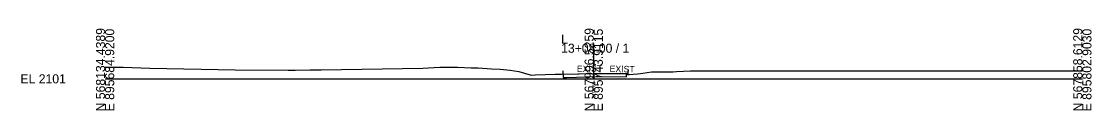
# Model space of a CAD drawing. Extents: x -26 to 1603, y -10 to 13527.
# Drawn here: x 1274.3 to 1602.8, y -9.7 to 15.4 of the extents above; entities that cross this region are included whole.
import ezdxf

# ---------------------------------------------------------------- set-up
doc = ezdxf.new("R2010")
doc.units = 0
for name, color, linetype in [('Default', 7, 'Continuous'), ('Exist XS Center Line Elevation Label', 7, 'Continuous'), ('Exist XS Ground Line', 7, 'Continuous'), ('Old_Level_61', 7, 'Continuous'), ('Old_Level_63', 7, 'Continuous'), ('Prop XS EOT Tick Mark', 7, 'Continuous'), ('Prop XS Finish Grade Pavement', 7, 'Continuous'), ('Prop XS Subgrade Earthwork', 7, 'Continuous')]:
    doc.layers.add(name, color=color, linetype=linetype)

msp = doc.modelspace()

# ---------------------------------------------------------------- linework, layer by layer
at = {"layer": 'Exist XS Ground Line'}
for p, q in [((1300, 3.54), (1300.91, 3.54)), ((1300, 3.54), (1300.91, 3.54)), ((1300.91, 3.54), (1305.5, 3.54)), ((1300.91, 3.54), (1305.5, 3.54)), ((1305.5, 3.54), (1313.77, 3.3)), ((1305.5, 3.54), (1313.77, 3.3)), ((1313.77, 3.3), (1339.93, 2.76)), ((1313.77, 3.3), (1339.93, 2.76)), ((1397.58, 3.24), (1402.75, 3.56)), ((1397.58, 3.24), (1402.75, 3.56)), ((1402.75, 3.56), (1404.84, 3.58)), ((1402.75, 3.56), (1404.84, 3.58)), ((1404.84, 3.58), (1406.91, 3.6)), ((1404.84, 3.58), (1406.91, 3.6)), ((1406.91, 3.6), (1408.21, 3.6)), ((1406.91, 3.6), (1408.21, 3.6)), ((1408.21, 3.6), (1412.37, 3.36)), ((1408.21, 3.6), (1412.37, 3.36)), ((1412.37, 3.36), (1413.97, 3.38)), ((1412.37, 3.36), (1413.97, 3.38)), ((1413.97, 3.38), (1414.55, 3.35)), ((1413.97, 3.38), (1414.55, 3.35)), ((1414.55, 3.35), (1418.66, 3.05)), ((1414.55, 3.35), (1418.66, 3.05)), ((1339.93, 2.76), (1356.24, 2.67)), ((1339.93, 2.76), (1356.24, 2.67)), ((1356.24, 2.67), (1357.3, 2.66)), ((1356.24, 2.67), (1357.3, 2.66)), ((1357.3, 2.66), (1358.38, 2.66)), ((1357.3, 2.66), (1358.38, 2.66)), ((1358.38, 2.66), (1362.94, 2.75)), ((1358.38, 2.66), (1362.94, 2.75)), ((1362.94, 2.75), (1363.26, 2.75)), ((1362.94, 2.75), (1363.26, 2.75)), ((1363.26, 2.75), (1366.29, 2.76)), ((1363.26, 2.75), (1366.29, 2.76)), ((1366.29, 2.76), (1397.58, 3.24)), ((1366.29, 2.76), (1397.58, 3.24)), ((1418.66, 3.05), (1421.26, 2.95)), ((1418.66, 3.05), (1421.26, 2.95)), ((1421.26, 2.95), (1424.33, 2.64)), ((1421.26, 2.95), (1424.33, 2.64)), ((1424.33, 2.64), (1427.05, 2.28)), ((1424.33, 2.64), (1427.05, 2.28)), ((1427.05, 2.28), (1430.45, 1.28)), ((1427.05, 2.28), (1430.45, 1.28)), ((1430.45, 1.28), (1430.89, 1.16)), ((1430.45, 1.28), (1430.89, 1.16)), ((1430.89, 1.16), (1431.99, 1.19)), ((1430.89, 1.16), (1431.99, 1.19)), ((1431.99, 1.19), (1438.2, 1.39)), ((1431.99, 1.19), (1438.2, 1.39)), ((1438.2, 1.39), (1440.11, 1.41)), ((1438.2, 1.39), (1440.11, 1.41)), ((1440.11, 1.41), (1450.1, 1.65)), ((1440.11, 1.41), (1450.1, 1.65)), ((1450.1, 1.65), (1450.79, 1.67)), ((1450.1, 1.65), (1450.79, 1.67)), ((1450.79, 1.67), (1451.38, 1.67)), ((1450.79, 1.67), (1451.38, 1.67)), ((1451.38, 1.67), (1460.05, 1.59)), ((1451.38, 1.67), (1460.05, 1.59)), ((1460.05, 1.59), (1460.36, 1.32)), ((1460.05, 1.59), (1460.36, 1.32)), ((1460.36, 1.32), (1460.86, 1.38)), ((1460.36, 1.32), (1460.86, 1.38)), ((1460.86, 1.38), (1462.09, 1.44)), ((1460.86, 1.38), (1462.09, 1.44)), ((1462.09, 1.44), (1463.42, 1.55)), ((1462.09, 1.44), (1463.42, 1.55)), ((1463.42, 1.55), (1464.39, 1.63)), ((1463.42, 1.55), (1464.39, 1.63)), ((1464.39, 1.63), (1465.09, 1.71)), ((1464.39, 1.63), (1465.09, 1.71)), ((1465.09, 1.71), (1467.77, 2.13)), ((1465.09, 1.71), (1467.77, 2.13)), ((1467.77, 2.13), (1468.19, 2.12)), ((1467.77, 2.13), (1468.19, 2.12)), ((1468.19, 2.12), (1472.25, 2.17)), ((1468.19, 2.12), (1472.25, 2.17)), ((1472.25, 2.17), (1473.72, 2.18)), ((1472.25, 2.17), (1473.72, 2.18)), ((1473.72, 2.18), (1474.07, 2.19)), ((1473.72, 2.18), (1474.07, 2.19)), ((1474.07, 2.19), (1474.42, 2.18)), ((1474.07, 2.19), (1474.42, 2.18)), ((1474.42, 2.18), (1475.38, 2.24)), ((1474.42, 2.18), (1475.38, 2.24)), ((1475.38, 2.24), (1479.67, 2.5)), ((1475.38, 2.24), (1479.67, 2.5)), ((1479.67, 2.5), (1482.42, 2.48)), ((1479.67, 2.5), (1482.42, 2.48)), ((1482.42, 2.48), (1483.99, 2.49)), ((1482.42, 2.48), (1483.99, 2.49)), ((1483.99, 2.49), (1497.19, 2.43)), ((1483.99, 2.49), (1497.19, 2.43)), ((1497.19, 2.43), (1498.98, 2.43)), ((1497.19, 2.43), (1498.98, 2.43)), ((1498.98, 2.43), (1509.07, 2.43)), ((1498.98, 2.43), (1509.07, 2.43)), ((1509.07, 2.43), (1514.01, 2.43)), ((1509.07, 2.43), (1514.01, 2.43)), ((1514.01, 2.43), (1515.32, 2.43)), ((1514.01, 2.43), (1515.32, 2.43)), ((1515.32, 2.43), (1518.03, 2.41)), ((1515.32, 2.43), (1518.03, 2.41)), ((1518.03, 2.41), (1529.72, 2.41)), ((1518.03, 2.41), (1529.72, 2.41)), ((1529.72, 2.41), (1533.82, 2.44)), ((1529.72, 2.41), (1533.82, 2.44)), ((1533.82, 2.44), (1535.06, 2.46)), ((1533.82, 2.44), (1535.06, 2.46)), ((1535.06, 2.46), (1539.24, 2.47)), ((1535.06, 2.46), (1539.24, 2.47)), ((1539.24, 2.47), (1539.83, 2.5)), ((1539.24, 2.47), (1539.83, 2.5)), ((1539.83, 2.5), (1545.51, 2.49)), ((1539.83, 2.5), (1545.51, 2.49)), ((1545.51, 2.49), (1550.52, 2.48)), ((1545.51, 2.49), (1550.52, 2.48)), ((1550.52, 2.48), (1552.49, 2.47)), ((1550.52, 2.48), (1552.49, 2.47)), ((1552.49, 2.47), (1553.73, 2.47)), ((1552.49, 2.47), (1553.73, 2.47)), ((1553.73, 2.47), (1561.79, 2.46)), ((1553.73, 2.47), (1561.79, 2.46)), ((1561.79, 2.46), (1568.55, 2.45)), ((1561.79, 2.46), (1568.55, 2.45)), ((1568.55, 2.45), (1569.89, 2.46)), ((1568.55, 2.45), (1569.89, 2.46)), ((1569.89, 2.46), (1571.6, 2.47)), ((1569.89, 2.46), (1571.6, 2.47)), ((1571.6, 2.47), (1585.89, 2.49)), ((1571.6, 2.47), (1585.89, 2.49)), ((1585.89, 2.49), (1586.74, 2.48)), ((1585.89, 2.49), (1586.74, 2.48)), ((1586.74, 2.48), (1598.45, 2.5)), ((1586.74, 2.48), (1598.45, 2.5)), ((1598.45, 2.5), (1600, 2.51)), ((1598.45, 2.5), (1600, 2.51))]:
    msp.add_line(p, q, dxfattribs=at)
at = {"layer": 'Old_Level_61'}
for p, q in [((1440.61, 1.42), (1440.61, 0.42)), ((1440.61, 0.42), (1441.61, 0.45)), ((1441.61, 0.45), (1450.73, 0.71)), ((1450.73, 0.71), (1451.19, 0.73)), ((1451.19, 0.73), (1451.59, 0.72)), ((1451.59, 0.72), (1460.05, 0.57)), ((1460.05, 0.57), (1460.05, 1.59))]:
    msp.add_line(p, q, dxfattribs=at)
at = {"layer": 'Old_Level_63'}
for p, q in [((1450, 0), (1450, 10.81)), ((1300, 0), (1450, 0)), ((1450, 0), (1600, 0))]:
    msp.add_line(p, q, dxfattribs=at)
at = {"layer": 'Prop XS EOT Tick Mark'}
for p, q in [((1440.61, 1.42), (1440.61, 2.42)), ((1460.55, 1.58), (1460.55, 2.58))]:
    msp.add_line(p, q, dxfattribs=at)
at = {"layer": 'Prop XS Finish Grade Pavement'}
for p, q in [((1440.61, 1.42), (1450.5, 1.67)), ((1450.5, 1.67), (1460.55, 1.58))]:
    msp.add_line(p, q, dxfattribs=at)
at = {"layer": 'Prop XS Subgrade Earthwork'}
for p, q in [((1440.16, 1.41), (1440.19, 1.38)), ((1440.19, 1.38), (1440.21, 1.45)), ((1440.21, 1.45), (1440.23, 1.41))]:
    msp.add_line(p, q, dxfattribs=at)

# ---------------------------------------------------------------- texts
at = {"layer": 'Default'}
for rotation, p in [(1.1458, (1444.84, 2.05)), (358.8542, (1454.84, 2.09))]:
    msp.add_text('EXIST', height=2, rotation=rotation, dxfattribs=at).set_placement(p)
at = {"layer": 'Exist XS Center Line Elevation Label'}
msp.add_text('2102.65', height=1, rotation=90, dxfattribs=at).set_placement((1450.5, -5.9))
at = {"layer": 'Old_Level_63'}
for s, p in [('N 568134.4389', (1300, -10)), ('E 895684.9200', (1302.8, -10)), ('N 567996.5259', (1450, -10)), ('E 895743.9115', (1452.8, -10)), ('N 567858.6129', (1600, -10)), ('E 895802.9030', (1602.8, -10))]:
    msp.add_text(s, height=2.8, rotation=90, dxfattribs=at).set_placement(p)
for s, p in [('L', (1440, 10.81)), ('13+08.00 / 1', (1440, 8.01)), ('EL 2101', (1274, -1.4))]:
    msp.add_text(s, height=2.8, dxfattribs=at).set_placement(p)

doc.saveas('drawing.dxf')
